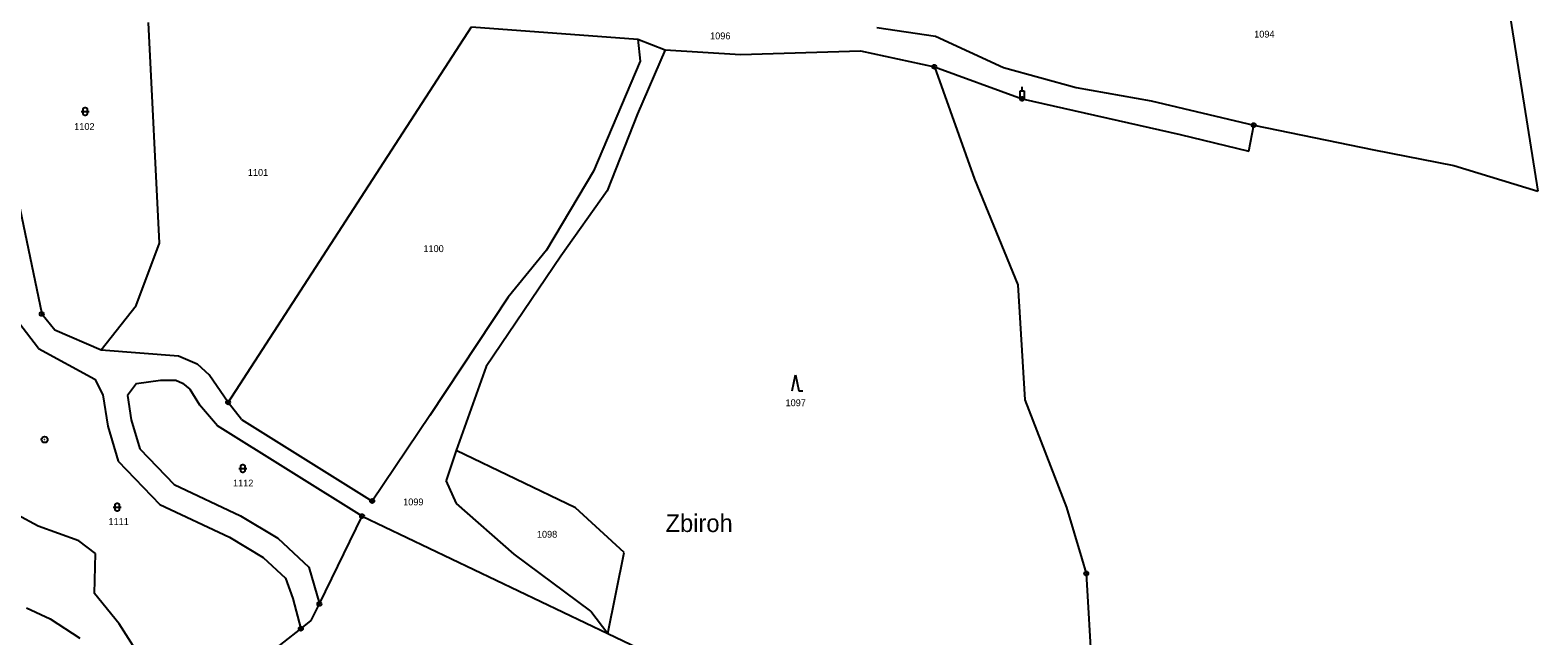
# Model space of a CAD drawing. Extents: x -796130 to -793145, y -1109506 to -1106267.
# Drawn here: x -794319.4 to -793944.8, y -1107878.4 to -1107727.8 of the extents above; entities that cross this region are included whole.
import ezdxf

# ---------------------------------------------------------------- set-up
doc = ezdxf.new("R2010")
doc.units = 0
for name, color, linetype in [('Vrstva 1', 7, 'Continuous'), ('Vrstva 14', 7, 'Continuous'), ('Vrstva 23', 7, 'Continuous'), ('Vrstva 26', 7, 'Continuous'), ('Vrstva 28', 7, 'Continuous'), ('Vrstva 39', 7, 'Continuous'), ('Vrstva 4', 7, 'Continuous')]:
    doc.layers.add(name, color=color, linetype=linetype)

msp = doc.modelspace()

# ---------------------------------------------------------------- linework, layer by layer
at = {"layer": 'Vrstva 1'}
for p, q in [((-794287.29, -1107780.75), (-794289.99, -1107725.94)), ((-794270.23, -1107820.33), (-794209.77, -1107726.99)), ((-794209.77, -1107726.99), (-794168.39, -1107730.01)), ((-794168.39, -1107730.01), (-794161.6, -1107732.71)), ((-794168.39, -1107730.01), (-794167.87, -1107735.54)), ((-794109.01, -1107727.19), (-794094.47, -1107729.3)), ((-794094.47, -1107729.3), (-794077.54, -1107737.07)), ((-794161.6, -1107732.71), (-794168.48, -1107748.59)), ((-794161.6, -1107732.71), (-794142.93, -1107733.86)), ((-794142.93, -1107733.86), (-794113.07, -1107732.99)), ((-794113.07, -1107732.99), (-794094.73, -1107736.92)), ((-794167.87, -1107735.54), (-794179.43, -1107762.87)), ((-794077.54, -1107737.07), (-794059.53, -1107742.07)), ((-794059.53, -1107742.07), (-794040.87, -1107745.34)), ((-794040.87, -1107745.34), (-794015.39, -1107751.42)), ((-794168.48, -1107748.59), (-794176.05, -1107767.73)), ((-794179.43, -1107762.87), (-794191.14, -1107782.51)), ((-794176.05, -1107767.73), (-794187.54, -1107783.97)), ((-794321.96, -1107772.05), (-794316.55, -1107798.35)), ((-794293.09, -1107796.22), (-794287.29, -1107780.75)), ((-794191.14, -1107782.51), (-794200.63, -1107794.15)), ((-794187.54, -1107783.97), (-794206.08, -1107811.42)), ((-794200.63, -1107794.15), (-794220.15, -1107823.56)), ((-794317.34, -1107806.92), (-794324.15, -1107798.06)), ((-794301.81, -1107807.28), (-794293.09, -1107796.22)), ((-794316.55, -1107798.35), (-794313.33, -1107802.32)), ((-794313.33, -1107802.32), (-794301.81, -1107807.28)), ((-794317.34, -1107806.92), (-794303.34, -1107814.56)), ((-794301.81, -1107807.28), (-794282.59, -1107808.77)), ((-794282.59, -1107808.77), (-794277.91, -1107810.73)), ((-794277.91, -1107810.73), (-794274.95, -1107813.5)), ((-794206.08, -1107811.42), (-794213.53, -1107832.27)), ((-794303.34, -1107814.56), (-794301.37, -1107818.41)), ((-794293.02, -1107815.66), (-794295.27, -1107818.64)), ((-794293.02, -1107815.66), (-794287.02, -1107814.77)), ((-794287.02, -1107814.77), (-794283.23, -1107814.77)), ((-794283.23, -1107814.77), (-794281.54, -1107815.52)), ((-794281.54, -1107815.52), (-794279.78, -1107817.08)), ((-794270.23, -1107820.33), (-794274.95, -1107813.5)), ((-794301.37, -1107818.41), (-794300.15, -1107826.21)), ((-794295.27, -1107818.64), (-794294.34, -1107824.69)), ((-794279.78, -1107817.08), (-794277.32, -1107820.94)), ((-794266.92, -1107824.56), (-794270.23, -1107820.33)), ((-794272.91, -1107826.13), (-794277.32, -1107820.94)), ((-794220.15, -1107823.56), (-794234.44, -1107844.84)), ((-794300.15, -1107826.21), (-794297.54, -1107834.96)), ((-794294.34, -1107824.69), (-794292.2, -1107831.86)), ((-794236.95, -1107848.59), (-794272.91, -1107826.13)), ((-794266.92, -1107824.56), (-794234.44, -1107844.84)), ((-794292.2, -1107831.86), (-794283.64, -1107840.75)), ((-794297.54, -1107834.96), (-794287.22, -1107845.69)), ((-794213.53, -1107832.27), (-794216.02, -1107839.71)), ((-794183.88, -1107846.53), (-794213.53, -1107832.27)), ((-794317.46, -1107851.08), (-794332.74, -1107842.87)), ((-794283.64, -1107840.75), (-794267.16, -1107848.49)), ((-794213.46, -1107845.43), (-794216.02, -1107839.71)), ((-794287.22, -1107845.69), (-794269.86, -1107853.85)), ((-794199.14, -1107858.02), (-794213.46, -1107845.43)), ((-794171.79, -1107857.62), (-794183.88, -1107846.53)), ((-794267.16, -1107848.49), (-794257.87, -1107854.11)), ((-794247.56, -1107870.43), (-794236.95, -1107848.59)), ((-794236.95, -1107848.59), (-794175.87, -1107877.74)), ((-794307.3, -1107854.71), (-794317.46, -1107851.08)), ((-794269.86, -1107853.85), (-794261.53, -1107858.9)), ((-794257.87, -1107854.11), (-794250.14, -1107861.28)), ((-794303.21, -1107857.89), (-794307.3, -1107854.71)), ((-794303.44, -1107867.8), (-794303.21, -1107857.89)), ((-794180.12, -1107872.24), (-794199.14, -1107858.02)), ((-794175.87, -1107877.74), (-794171.79, -1107857.62)), ((-794261.53, -1107858.9), (-794255.98, -1107864.05)), ((-794250.14, -1107861.28), (-794247.56, -1107870.43)), ((-794255.98, -1107864.05), (-794254.13, -1107869.09)), ((-794297.29, -1107875.35), (-794303.44, -1107867.8)), ((-794254.13, -1107869.09), (-794252.16, -1107876.59)), ((-794320.31, -1107871.41), (-794314.42, -1107874.11)), ((-794249.56, -1107874.54), (-794247.56, -1107870.43)), ((-794180.12, -1107872.24), (-794175.87, -1107877.74)), ((-794314.42, -1107874.11), (-794307.09, -1107878.97)), ((-794292.06, -1107883.61), (-794297.29, -1107875.35)), ((-794260.61, -1107883.26), (-794252.16, -1107876.59)), ((-794252.16, -1107876.59), (-794249.56, -1107874.54)), ((-794175.87, -1107877.74), (-794108.67, -1107909.82))]:
    msp.add_line(p, q, dxfattribs=at)
at = {"layer": 'Vrstva 23'}
for p, q in [((-794306.76, -1107748.01), (-794304.76, -1107748.01)), ((-794306.26, -1107747.41), (-794306.16, -1107747.21)), ((-794306.26, -1107748.61), (-794306.26, -1107747.41)), ((-794306.16, -1107748.81), (-794306.26, -1107748.61)), ((-794306.16, -1107747.21), (-794306.06, -1107747.11)), ((-794306.06, -1107748.91), (-794306.16, -1107748.81)), ((-794306.06, -1107747.11), (-794305.86, -1107747.01)), ((-794305.86, -1107749.01), (-794306.06, -1107748.91)), ((-794305.86, -1107747.01), (-794305.66, -1107747.01)), ((-794305.66, -1107749.01), (-794305.86, -1107749.01)), ((-794305.66, -1107747.01), (-794305.46, -1107747.11)), ((-794305.46, -1107748.91), (-794305.66, -1107749.01)), ((-794305.46, -1107747.11), (-794305.36, -1107747.21)), ((-794305.36, -1107748.81), (-794305.46, -1107748.91)), ((-794305.36, -1107747.21), (-794305.26, -1107747.41)), ((-794305.26, -1107748.61), (-794305.36, -1107748.81)), ((-794305.26, -1107747.41), (-794305.26, -1107748.61)), ((-794130.04, -1107817.48), (-794129.24, -1107813.48)), ((-794129.24, -1107813.48), (-794128.44, -1107817.48)), ((-794128.44, -1107817.48), (-794127.44, -1107817.48)), ((-794267.59, -1107836.73), (-794265.59, -1107836.73)), ((-794267.09, -1107836.13), (-794266.99, -1107835.93)), ((-794267.09, -1107837.33), (-794267.09, -1107836.13)), ((-794266.99, -1107837.53), (-794267.09, -1107837.33)), ((-794266.99, -1107835.93), (-794266.89, -1107835.83)), ((-794266.89, -1107837.63), (-794266.99, -1107837.53)), ((-794266.89, -1107835.83), (-794266.69, -1107835.73)), ((-794266.69, -1107837.73), (-794266.89, -1107837.63)), ((-794266.69, -1107835.73), (-794266.49, -1107835.73)), ((-794266.49, -1107837.73), (-794266.69, -1107837.73)), ((-794266.49, -1107835.73), (-794266.29, -1107835.83)), ((-794266.29, -1107837.63), (-794266.49, -1107837.73)), ((-794266.29, -1107835.83), (-794266.19, -1107835.93)), ((-794266.19, -1107837.53), (-794266.29, -1107837.63)), ((-794266.19, -1107835.93), (-794266.09, -1107836.13)), ((-794266.09, -1107837.33), (-794266.19, -1107837.53)), ((-794266.09, -1107836.13), (-794266.09, -1107837.33)), ((-794298.79, -1107846.36), (-794296.79, -1107846.36)), ((-794298.29, -1107845.76), (-794298.19, -1107845.56)), ((-794298.29, -1107846.96), (-794298.29, -1107845.76)), ((-794298.19, -1107845.56), (-794298.09, -1107845.46)), ((-794298.09, -1107845.46), (-794297.89, -1107845.36)), ((-794297.89, -1107845.36), (-794297.69, -1107845.36)), ((-794297.69, -1107845.36), (-794297.49, -1107845.46)), ((-794297.49, -1107845.46), (-794297.39, -1107845.56)), ((-794297.39, -1107845.56), (-794297.29, -1107845.76)), ((-794297.29, -1107845.76), (-794297.29, -1107846.96)), ((-794298.19, -1107847.16), (-794298.29, -1107846.96)), ((-794298.09, -1107847.26), (-794298.19, -1107847.16)), ((-794297.89, -1107847.36), (-794298.09, -1107847.26)), ((-794297.69, -1107847.36), (-794297.89, -1107847.36)), ((-794297.49, -1107847.26), (-794297.69, -1107847.36)), ((-794297.39, -1107847.16), (-794297.49, -1107847.26)), ((-794297.29, -1107846.96), (-794297.39, -1107847.16))]:
    msp.add_line(p, q, dxfattribs=at)
at = {"layer": 'Vrstva 26'}
for p, q in [((-794072.95, -1107742.86), (-794072.95, -1107741.86)), ((-794073.45, -1107744.86), (-794073.45, -1107742.86)), ((-794073.45, -1107742.86), (-794072.45, -1107742.86)), ((-794073.45, -1107744.76), (-794073.35, -1107744.56)), ((-794073.45, -1107744.96), (-794073.45, -1107744.76)), ((-794073.35, -1107745.16), (-794073.45, -1107744.96)), ((-794073.35, -1107744.56), (-794073.25, -1107744.46)), ((-794073.25, -1107745.26), (-794073.35, -1107745.16)), ((-794073.25, -1107744.46), (-794073.05, -1107744.36)), ((-794073.05, -1107745.36), (-794073.25, -1107745.26)), ((-794073.05, -1107744.36), (-794072.85, -1107744.36)), ((-794072.85, -1107745.36), (-794073.05, -1107745.36)), ((-794072.95, -1107744.86), (-794072.95, -1107744.86)), ((-794072.85, -1107744.36), (-794072.65, -1107744.46)), ((-794072.65, -1107745.26), (-794072.85, -1107745.36)), ((-794072.65, -1107744.46), (-794072.55, -1107744.56)), ((-794072.55, -1107745.16), (-794072.65, -1107745.26)), ((-794072.55, -1107744.56), (-794072.45, -1107744.76)), ((-794072.45, -1107744.96), (-794072.55, -1107745.16)), ((-794072.45, -1107742.86), (-794072.45, -1107744.86)), ((-794072.45, -1107744.76), (-794072.45, -1107744.96))]:
    msp.add_line(p, q, dxfattribs=at)
at = {"layer": 'Vrstva 28'}
for centre, radius in [((-794094.73, -1107736.92), 0.5), ((-794094.73, -1107736.92), 0.01), ((-794015.39, -1107751.42), 0.5), ((-794015.39, -1107751.42), 0.01), ((-794316.55, -1107798.35), 0.5), ((-794316.55, -1107798.35), 0.01), ((-794270.23, -1107820.33), 0.5), ((-794270.23, -1107820.33), 0.01), ((-794315.84, -1107829.57), 0.75), ((-794315.84, -1107829.57), 0.01), ((-794234.44, -1107844.84), 0.5), ((-794234.44, -1107844.84), 0.01), ((-794236.95, -1107848.59), 0.5), ((-794236.95, -1107848.59), 0.5), ((-794236.95, -1107848.59), 0.01), ((-794236.95, -1107848.59), 0.01), ((-794057, -1107862.86), 0.5), ((-794057, -1107862.86), 0.01), ((-794247.56, -1107870.43), 0.5), ((-794247.56, -1107870.43), 0.5), ((-794247.56, -1107870.43), 0.01), ((-794247.56, -1107870.43), 0.01), ((-794252.16, -1107876.59), 0.5), ((-794252.16, -1107876.59), 0.5), ((-794252.16, -1107876.59), 0.01), ((-794252.16, -1107876.59), 0.01)]:
    msp.add_circle(centre, radius, dxfattribs=at)
at = {"layer": 'Vrstva 4'}
for p, q in [((-793952.73, -1107718.05), (-793944.79, -1107767.86)), ((-794094.73, -1107736.92), (-794072.95, -1107744.86)), ((-794094.73, -1107736.92), (-794084.77, -1107764.88)), ((-794072.95, -1107744.86), (-794033.65, -1107753.73)), ((-794016.6, -1107757.88), (-794015.39, -1107751.42)), ((-794015.39, -1107751.42), (-793985.54, -1107757.52)), ((-794033.65, -1107753.73), (-794016.6, -1107757.88)), ((-793985.54, -1107757.52), (-793965.68, -1107761.41)), ((-793965.68, -1107761.41), (-793944.79, -1107767.86)), ((-794084.77, -1107764.88), (-794074.02, -1107791.1)), ((-794074.02, -1107791.1), (-794072.24, -1107819.7)), ((-794072.24, -1107819.7), (-794061.93, -1107846.48)), ((-794061.93, -1107846.48), (-794058.1, -1107859.21)), ((-794058.1, -1107859.21), (-794057, -1107862.86)), ((-794057, -1107862.86), (-794055.44, -1107890.22))]:
    msp.add_line(p, q, dxfattribs=at)

# ---------------------------------------------------------------- texts
at = {"layer": 'Vrstva 14'}
for s, p in [('1096', (-794150.469, -1107730.08)), ('1094', (-794015.275, -1107729.65)), ('1102', (-794308.482, -1107752.61)), ('1101', (-794265.335, -1107764.03)), ('1100', (-794221.711, -1107782.97)), ('1097', (-794131.726, -1107821.27)), ('1112', (-794269.016, -1107841.23)), ('1099', (-794226.739, -1107845.92)), ('1111', (-794299.959, -1107850.79)), ('1098', (-794193.509, -1107853.96))]:
    msp.add_text(s, height=1.7, dxfattribs=at).set_placement(p)
at = {"layer": 'Vrstva 39'}
msp.add_text('Zbiroh', height=4.4, dxfattribs=at).set_placement((-794161.53, -1107852.55))

doc.saveas('drawing.dxf')
